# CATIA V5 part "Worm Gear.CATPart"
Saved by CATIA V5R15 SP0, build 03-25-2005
Part number: Gear_Worm
Bounding box of the stored display mesh (mm): x 0 to 155, y -49.25 to 49.25, z -49.25 to 49.25
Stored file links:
  E:\#01 CATIA Lecture Materials\#06 DMU\#11 DMU Page01 KIN EX11\Worm Gear.CATPart
  E:\V5_education\CATIA Data\KIN\Under Motor\Motor.CATPart
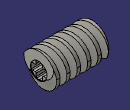
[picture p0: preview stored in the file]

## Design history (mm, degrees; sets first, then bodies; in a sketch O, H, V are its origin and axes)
Body1 (main body)
  Sketch1 on yz-plane, origin (0, 0, 0), H (0, 1, 0), V (0, 0, 1)
    circle A1 centre (0, 0) radius 49.25
    radius A1 = 49.25
  Pad1: profile Sketch1, direction (1, 0, 0), length 155
  Sketch2 on start face of Pad1, origin (0, 0, 0), H (0, -1, 0), V (0, 0, 1)
    arc A1 centre (0, 0) radius 23.8 from (0, 23.8) to (-7.1514, 22.7002) ccw
    point P1 (0, 0)
    line L1 (-19.8388, 9.25) -> (-12.25, 9.25)
    line L2 (-9.25, -19.8388) -> (-9.25, -12.25)
    line L3 (-9.25, 12.25) -> (-9.25, 19.8388)
    line L4 (-12.25, -9.25) -> (-19.8388, -9.25)
    arc A2 centre (0, 0) radius 23.8 from (-22.7002, 7.1514) to (-22.7002, -7.1514) ccw
    arc A3 centre (0, 0) radius 23.8 from (-7.1514, -22.7002) to (0, -23.8) ccw
    axis line L5 (0, -2.0687) -> (0, -8.3393)
    point P2 (0, -2.0687)
    point P3 (0, -8.3393)
    point P4 (0, 23.8)
    point P5 (0, -23.8)
    arc A4 centre (-6.25, -19.8388) radius 3 from (-7.1514, -22.7002) to (-9.25, -19.8388) cw
    point P6 (-7.1514, -22.7002)
    point P7 (-9.25, -19.8388)
    arc A5 centre (-19.8388, -6.25) radius 3 from (-22.7002, -7.1514) to (-19.8388, -9.25) ccw
    point P9 (-22.7002, -7.1514)
    point P10 (-19.8388, -9.25)
    arc A6 centre (-19.8388, 6.25) radius 3 from (-22.7002, 7.1514) to (-19.8388, 9.25) cw
    point P12 (-22.7002, 7.1514)
    point P13 (-19.8388, 9.25)
    arc A7 centre (-12.25, -12.25) radius 3 from (-9.25, -12.25) to (-12.25, -9.25) ccw
    point P15 (-9.25, -12.25)
    point P16 (-12.25, -9.25)
    arc A8 centre (-12.25, 12.25) radius 3 from (-12.25, 9.25) to (-9.25, 12.25) ccw
    point P18 (-12.25, 9.25)
    point P19 (-9.25, 12.25)
    arc A9 centre (-6.25, 19.8388) radius 3 from (-7.1514, 22.7002) to (-9.25, 19.8388) ccw
    point P21 (-7.1514, 22.7002)
    point P22 (-9.25, 19.8388)
    point P24 (0, 0)
    point P25 (0, -8.3393)
    point P26 (0, 23.8)
    point P27 (0, -23.8)
    point P28 (7.1514, -22.7002)
    point P29 (9.25, -19.8388)
    point P31 (22.7002, -7.1514)
    point P32 (19.8388, -9.25)
    point P34 (22.7002, 7.1514)
    point P35 (19.8388, 9.25)
    point P37 (9.25, -12.25)
    point P38 (12.25, -9.25)
    point P40 (12.25, 9.25)
    point P41 (9.25, 12.25)
    point P43 (7.1514, 22.7002)
    point P44 (9.25, 19.8388)
    arc A10 centre (0, 0) radius 23.8 from (0, 23.8) to (7.1514, 22.7002) cw
    line L6 (19.8388, 9.25) -> (12.25, 9.25)
    line L7 (9.25, -19.8388) -> (9.25, -12.25)
    line L8 (9.25, 12.25) -> (9.25, 19.8388)
    line L9 (12.25, -9.25) -> (19.8388, -9.25)
    arc A11 centre (0, 0) radius 23.8 from (22.7002, 7.1514) to (22.7002, -7.1514) cw
    arc A12 centre (0, 0) radius 23.8 from (7.1514, -22.7002) to (0, -23.8) cw
    arc A13 centre (6.25, -19.8388) radius 3 from (7.1514, -22.7002) to (9.25, -19.8388) ccw
    arc A14 centre (19.8388, -6.25) radius 3 from (22.7002, -7.1514) to (19.8388, -9.25) cw
    arc A15 centre (19.8388, 6.25) radius 3 from (22.7002, 7.1514) to (19.8388, 9.25) ccw
    arc A16 centre (12.25, -12.25) radius 3 from (9.25, -12.25) to (12.25, -9.25) cw
    arc A17 centre (12.25, 12.25) radius 3 from (12.25, 9.25) to (9.25, 12.25) cw
    arc A18 centre (6.25, 19.8388) radius 3 from (7.1514, 22.7002) to (9.25, 19.8388) cw
    radius A1 = 23.8
    distance L2 L5 = 9.25
    distance L1 L4 = 18.5
    radius A4 = 3 {= Sketch2.radius(A9)}
    radius A5 = 3 {= Sketch2.radius(A9)}
    radius A6 = 3 {= Sketch2.radius(A9)}
    radius A7 = 3 {= Sketch2.radius(A9)}
    radius A8 = 3 {= Sketch2.radius(A9)}
    radius A9 = 3
    horizontal: L1 H, L4 H
    vertical: L2 V, L3 V, L5 V
    coincidence: L2 L3, A1 A2, A2 A3, P2 V, L5 P4, L5 P5, P4 P26, P5 P27, P24 O
    equidistance: L1 L4 P1
    tangency: A4 A3, A4 L2, A5 L4, A5 A2, A6 L1, A6 A2, A7 L2, A7 L4, A8 L1, A8 L3, A9 A1, A9 L3
    symmetry: P3 P25 L5, P4 P26 L5, P5 P27 L5, P6 P28 L5, P7 P29 L5, P9 P31 L5, P10 P32 L5, P12 P34 L5, P13 P35 L5, P15 P37 L5, P16 P38 L5, P18 P40 L5, P19 P41 L5, P21 P43 L5, P22 P44 L5, A1 A10 L5, L1 L6 L5, L2 L7 L5, L3 L8 L5, L4 L9 L5, A2 A11 L5, A3 A12 L5, A4 A13 L5, A5 A14 L5, A6 A15 L5, A7 A16 L5, A8 A17 L5, A9 A18 L5
  Pocket1: profile Sketch2, direction (1, 0, 0), length 155 {= Pad1.FirstLimit.Length}
  Sketch3 on yz-plane, origin (0, 0, 0), H (0, 1, 0), V (0, 0, 1)
    circle A1 centre (0, 0) radius 23.8
    reference projected arc E1 centre (0, 0) radius 23.8 from (7.1514, 22.7002) to (0, 23.8) ccw from edge [face of Pocket1 from Sketch2.A1 | end face of Pad1]
    coincidence: A1 E1
  Pocket2: profile Sketch3, direction (1, 0, 0), length 2
  Sketch4 on end face of Pad1, origin (155, 0, 0), H (0, 1, 0), V (0, 0, 1)
    circle A1 centre (0, 0) radius 23.8
    reference projected arc E1 centre (0, 0) radius 23.8 from (7.1514, 22.7002) to (0, 23.8) ccw from edge [face of Pocket1 from Sketch2.A1 | end face of Pad1]
    coincidence: A1 E1
  Pocket3: profile Sketch4, direction (-1, 0, 0), length 2
  Sketch5 on zx-plane, origin (0, 0, 0), H (-1, 0, 0), V (0, 0, 1)
    line L1 (20, 49.25) -> (0, 49.25)
    line L2 (0, 49.25) -> (5, 25)
    line L3 (5, 25) -> (15, 25)
    line L4 (15, 25) -> (20, 49.25)
    construction line L5 (10, 5.593) -> (10, -0.8276)
    axis line L6 (6.2945, 0) -> (-17.771, 0)
    point P7 (6.2945, 0)
    point P9 (10, 48.25)
    length L1 = 20
    length L3 = 10
    distance L3 H = 25
    distance L1 H = 49.25 {= Sketch1.radius(A1)}
    distance L5 V = 10
    distance P9 L1 = 1
    horizontal: L1 H, L3 H, L6 H
    vertical: L5 V
    symmetry: L2 L4 L5
    coincidence: P7 H, P9 L5
  Sketch6 on zx-plane, origin (0, 0, 0), H (-1, 0, 0), V (0, 0, 1)
    point P1 (10, 36.75)
    reference projected line E1 (20, 49.25) -> (0, 49.25) from Sketch5.L1
    reference projected line E2 (15, 25) -> (20, 49.25) from Sketch5.L4
    reference projected line E3 (0, 49.25) -> (5, 25) from Sketch5.L2
    construction line L1 (6.6592, 0) -> (-17.4956, 0)
    point P2 (6.6592, 0)
    distance E1 P1 = 12.5
    equidistance: E2 E3 P1
    coincidence: P2 H
    horizontal: L1 H
  Helix1: Direction Sketch6.H, RefPoint Sketch6, Pitch 30, Height 195, TaperAngle 0
  Slot1: profile Sketch5, centre curve Helix1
